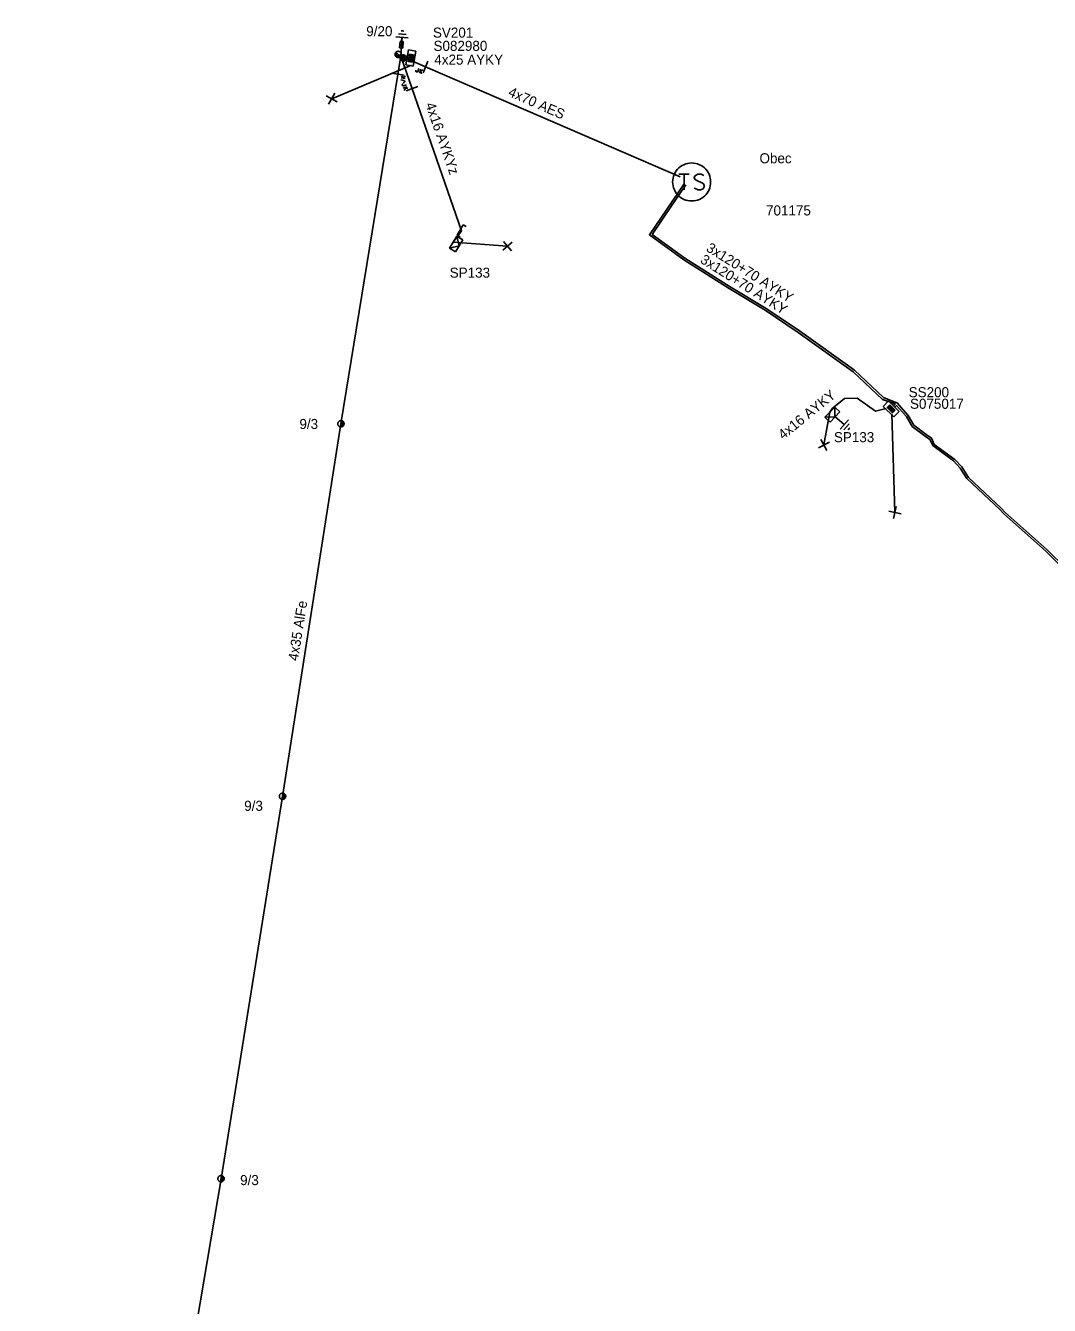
# Model space of a CAD drawing. Extents: x -788458 to -786145, y -1154772 to -1152372.
# Drawn here: x -786583.3 to -786481.4, y -1153446 to -1153318.7 of the extents above; entities that cross this region are included whole.
import ezdxf

# ---------------------------------------------------------------- set-up
doc = ezdxf.new("R2010")
doc.units = 0
for name, color, linetype in [('Vrstva 1', 7, 'Continuous'), ('Vrstva 12', 7, 'Continuous'), ('Vrstva 13', 7, 'Continuous'), ('Vrstva 14', 7, 'Continuous'), ('Vrstva 15', 7, 'Continuous'), ('Vrstva 16', 7, 'Continuous'), ('Vrstva 18', 7, 'Continuous'), ('Vrstva 2', 7, 'Continuous'), ('Vrstva 25', 7, 'Continuous'), ('Vrstva 26', 7, 'Continuous'), ('Vrstva 27', 7, 'Continuous'), ('Vrstva 28', 7, 'Continuous'), ('Vrstva 29', 7, 'Continuous'), ('Vrstva 30', 7, 'Continuous'), ('Vrstva 31', 7, 'Continuous'), ('Vrstva 33', 7, 'Continuous'), ('Vrstva 34', 7, 'Continuous'), ('Vrstva 5', 7, 'Continuous'), ('Vrstva 50', 7, 'Continuous'), ('Vrstva 51', 7, 'Continuous'), ('Vrstva 52', 7, 'Continuous'), ('Vrstva 54', 7, 'Continuous'), ('Vrstva 55', 7, 'Continuous'), ('Vrstva 59', 7, 'Continuous'), ('Vrstva 6', 7, 'Continuous'), ('Vrstva 8', 7, 'Continuous'), ('Vrstva 9', 7, 'Continuous')]:
    doc.layers.add(name, color=color, linetype=linetype)

# ---------------------------------------------------------------- blocks, each defined once
blk = doc.blocks.new('NN440')
at = {"layer": 'Vrstva 2'}
for points in [[(0.63, 0), (0.63, 0.06), (0.62, 0.13), (0.6, 0.19), (0.58, 0.25), (0.55, 0.31), (0.51, 0.37), (0.47, 0.42), (0.42, 0.46), (0.37, 0.51), (0.32, 0.54), (0.26, 0.57), (0.2, 0.59), (0.13, 0.61), (0.07, 0.62), (0, 0.63), (-0.06, 0.62), (-0.13, 0.61), (-0.19, 0.59), (-0.26, 0.57), (-0.31, 0.54), (-0.37, 0.51), (-0.42, 0.46), (-0.47, 0.42), (-0.51, 0.37), (-0.54, 0.31), (-0.57, 0.25), (-0.6, 0.19), (-0.62, 0.13), (-0.63, 0.06), (-0.63, 0), (-0.63, -0.07), (-0.62, -0.14), (-0.6, -0.2), (-0.57, -0.26), (-0.54, -0.32), (-0.51, -0.37), (-0.47, -0.43), (-0.42, -0.47), (-0.37, -0.51), (-0.31, -0.55), (-0.26, -0.58), (-0.19, -0.6), (-0.13, -0.62), (-0.06, -0.63), (0, -0.63), (0.07, -0.63), (0.13, -0.62), (0.2, -0.6), (0.26, -0.58), (0.32, -0.55), (0.37, -0.51), (0.42, -0.47), (0.47, -0.43), (0.51, -0.37), (0.55, -0.32), (0.58, -0.26), (0.6, -0.2), (0.62, -0.14), (0.63, -0.07), (0.63, 0)], [(-0.63, 0), (0.63, 0)], [(-0.6, -0.18), (0.57, -0.18)], [(-0.51, -0.32), (0.5, -0.32)], [(-0.37, -0.47), (0.35, -0.47)]]:
    blk.add_lwpolyline(points, dxfattribs=at)
blk = doc.blocks.new('NN450')
at = {"layer": 'Vrstva 2'}
for points in [[(0, 0), (0, 0.07), (-0.01, 0.13), (-0.03, 0.19), (-0.05, 0.25), (-0.08, 0.31), (-0.12, 0.37), (-0.16, 0.42), (-0.21, 0.46), (-0.26, 0.51), (-0.31, 0.54), (-0.37, 0.57), (-0.43, 0.59), (-0.5, 0.61), (-0.56, 0.62), (-0.63, 0.62), (-0.69, 0.62), (-0.75, 0.61), (-0.82, 0.59), (-0.88, 0.57), (-0.94, 0.54), (-0.99, 0.51), (-1.04, 0.46), (-1.09, 0.42), (-1.13, 0.37), (-1.17, 0.31), (-1.2, 0.25), (-1.22, 0.19), (-1.24, 0.13), (-1.25, 0.07), (-1.25, 0), (-1.25, -0.07), (-1.24, -0.13), (-1.22, -0.19), (-1.2, -0.25), (-1.17, -0.31), (-1.13, -0.37), (-1.09, -0.42), (-1.04, -0.46), (-0.99, -0.51), (-0.94, -0.54), (-0.88, -0.57), (-0.82, -0.59), (-0.75, -0.61), (-0.69, -0.62), (-0.62, -0.63), (-0.56, -0.62), (-0.5, -0.61), (-0.43, -0.59), (-0.37, -0.57), (-0.31, -0.54), (-0.26, -0.51), (-0.21, -0.46), (-0.16, -0.42), (-0.12, -0.37), (-0.08, -0.31), (-0.05, -0.25), (-0.03, -0.19), (-0.01, -0.13), (0, -0.07), (0, 0)], [(1.25, 0), (1.25, 0.07), (1.24, 0.13), (1.22, 0.19), (1.2, 0.25), (1.17, 0.31), (1.13, 0.37), (1.09, 0.42), (1.04, 0.46), (0.99, 0.51), (0.94, 0.54), (0.88, 0.57), (0.82, 0.59), (0.75, 0.61), (0.69, 0.62), (0.62, 0.62), (0.56, 0.62), (0.5, 0.61), (0.43, 0.59), (0.37, 0.57), (0.31, 0.54), (0.26, 0.51), (0.21, 0.46), (0.16, 0.42), (0.12, 0.37), (0.08, 0.31), (0.05, 0.25), (0.03, 0.19), (0.01, 0.13), (0, 0.07), (0, 0), (0, -0.07), (0.01, -0.13), (0.03, -0.19), (0.05, -0.25), (0.08, -0.31), (0.12, -0.37), (0.16, -0.42), (0.21, -0.46), (0.26, -0.51), (0.31, -0.54), (0.37, -0.57), (0.43, -0.59), (0.5, -0.61), (0.56, -0.62), (0.63, -0.63), (0.69, -0.62), (0.75, -0.61), (0.82, -0.59), (0.88, -0.57), (0.94, -0.54), (0.99, -0.51), (1.04, -0.46), (1.09, -0.42), (1.13, -0.37), (1.17, -0.31), (1.2, -0.25), (1.22, -0.19), (1.24, -0.13), (1.25, -0.07), (1.25, 0)], [(-1.25, 0), (1.25, 0)], [(-1.23, -0.16), (-0.02, -0.16)], [(-1.16, -0.32), (-0.09, -0.32)], [(-1.03, -0.47), (-0.22, -0.47)], [(0.02, -0.16), (1.23, -0.16)], [(0.09, -0.32), (1.16, -0.32)], [(0.22, -0.47), (1.03, -0.47)]]:
    blk.add_lwpolyline(points, dxfattribs=at)
blk = doc.blocks.new('NN840')
at = {"layer": 'Vrstva 15'}
for points in [[(0, 0.62), (0, -0.63)], [(-0.75, -0.71), (-0.75, -0.66)], [(-0.73, -0.76), (-0.75, -0.71)], [(-0.66, -0.8), (-0.73, -0.76)], [(-0.63, -0.8), (-0.66, -0.8)], [(-0.56, -0.76), (-0.63, -0.8)], [(-0.54, -0.71), (-0.56, -0.76)], [(-0.54, -0.38), (-0.54, -0.71)], [(-0.33, -0.38), (-0.33, -0.8)], [(-0.33, -0.64), (-0.13, -0.38)], [(-0.26, -0.56), (-0.09, -0.8)]]:
    blk.add_lwpolyline(points, dxfattribs=at)
blk = doc.blocks.new('NN800')
at = {"layer": 'Vrstva 1'}
for points in [[(-0.44, 0.44), (0.44, -0.44)], [(-0.44, -0.44), (0.44, 0.44)]]:
    blk.add_lwpolyline(points, dxfattribs=at)
blk = doc.blocks.new('NN820')
at = {"layer": 'Vrstva 13'}
for points in [[(0, 0), (0, -1.05)], [(-0.16, -0.81), (0.16, -0.81)], [(-0.16, -1.47), (-0.16, -0.81)], [(0, -1.05), (-0.06, -0.93)], [(0, -1.05), (0.06, -0.93)], [(0.16, -0.81), (0.16, -1.47)], [(0.16, -1.47), (-0.16, -1.47)], [(0, -1.47), (0, -1.87)]]:
    blk.add_lwpolyline(points, dxfattribs=at)
blk = doc.blocks.new('NN620')
at = {"layer": 'Vrstva 8'}
for points in [[(0.75, 0), (-0.75, 0)], [(-0.75, 0), (-0.75, -0.75)], [(0.75, -0.75), (0.75, 0)], [(-0.75, -0.75), (0.75, -0.75)], [(0.37, -0.18), (-0.38, -0.18)], [(-0.38, -0.18), (-0.38, -0.56)], [(-0.38, -0.56), (0.37, -0.56)], [(0.32, -0.23), (-0.33, -0.23)], [(-0.33, -0.23), (-0.33, -0.51)], [(-0.33, -0.51), (0.32, -0.51)], [(0.27, -0.27), (-0.28, -0.27)], [(-0.28, -0.27), (-0.28, -0.46)], [(-0.28, -0.46), (0.27, -0.46)], [(0.23, -0.32), (-0.23, -0.32)], [(-0.23, -0.32), (-0.23, -0.42)], [(-0.23, -0.42), (0.23, -0.42)], [(-0.19, -0.37), (0.19, -0.37)], [(0.23, -0.42), (0.23, -0.32)], [(0.27, -0.46), (0.27, -0.27)], [(0.32, -0.51), (0.32, -0.23)], [(0.37, -0.56), (0.37, -0.18)]]:
    blk.add_lwpolyline(points, dxfattribs=at)
blk = doc.blocks.new('NN630')
at = {"layer": 'Vrstva 9'}
for points in [[(0, -0.7), (-0.7, 0)], [(-0.7, -0.7), (-0.7, 0), (0.7, 0), (0.7, -0.7)], [(-0.7, -0.7), (0.7, -0.7)], [(0, -0.7), (0.7, 0)]]:
    blk.add_lwpolyline(points, dxfattribs=at)
blk = doc.blocks.new('NN810')
at = {"layer": 'Vrstva 14'}
for points in [[(0, -0.64), (0, -1.89)], [(0.63, -1.89), (-0.62, -1.89)], [(0.39, -2.2), (-0.4, -2.2)], [(0, -2.52), (-0.12, -2.52)], [(0.14, -2.52), (0, -2.52)]]:
    blk.add_lwpolyline(points, dxfattribs=at)
blk = doc.blocks.new('NN610')
at = {"layer": 'Vrstva 6'}
for points in [[(1.88, 0), (1.87, 0.2), (1.84, 0.39), (1.79, 0.58), (1.72, 0.77), (1.63, 0.94), (1.52, 1.11), (1.4, 1.26), (1.26, 1.4), (1.1, 1.53), (0.94, 1.63), (0.76, 1.72), (0.58, 1.8), (0.19, 1.88), (0.19, 1.88), (-0.01, 1.89), (-0.21, 1.88), (-0.4, 1.85), (-0.59, 1.8), (-0.78, 1.72), (-0.95, 1.63), (-1.12, 1.53), (-1.27, 1.4), (-1.41, 1.26), (-1.54, 1.11), (-1.64, 0.94), (-1.73, 0.77), (-1.8, 0.58), (-1.86, 0.39), (-1.89, 0.2), (-1.9, 0), (-1.89, -0.2), (-1.86, -0.39), (-1.8, -0.58), (-1.73, -0.77), (-1.64, -0.95), (-1.54, -1.11), (-1.41, -1.27), (-1.27, -1.41), (-1.12, -1.53), (-0.95, -1.64), (-0.78, -1.73), (-0.59, -1.8), (-0.4, -1.85), (-0.21, -1.88), (-0.01, -1.89), (0.19, -1.88), (0.39, -1.85), (0.58, -1.8), (0.76, -1.73), (0.94, -1.64), (1.1, -1.53), (1.26, -1.41), (1.4, -1.27), (1.52, -1.11), (1.63, -0.95), (1.72, -0.77), (1.79, -0.58), (1.84, -0.39), (1.87, -0.2), (1.88, 0)], [(-1.27, 0.78), (-0.26, 0.78)], [(-0.76, 0.78), (-0.76, -0.79)], [(1.19, 0.66), (0.94, 0.78), (0.62, 0.78), (0.37, 0.66), (0.24, 0.47), (0.24, 0.4), (0.37, 0.22), (1.12, -0.16), (1.25, -0.32), (1.25, -0.48), (1.12, -0.67), (0.87, -0.79), (0.62, -0.79), (0.49, -0.73), (0.24, -0.6)]]:
    blk.add_lwpolyline(points, dxfattribs=at)
blk = doc.blocks.new('NN515')
at = {"layer": 'Vrstva 2'}
for points in [[(-0.59, 0.18), (0.59, 0.18)], [(-0.59, 0.18), (-0.59, -0.18)], [(0.59, 0.18), (0.59, -0.18)]]:
    blk.add_lwpolyline(points, dxfattribs=at)

msp = doc.modelspace()

# ---------------------------------------------------------------- linework, layer by layer
at = {"layer": 'Vrstva 1'}
msp.add_lwpolyline([(-786489.69, -1153518.84), (-786509.16, -1153535.21), (-786526.82, -1153550.01), (-786583.29, -1153546.79), (-786577.19, -1153510.6), (-786570.4, -1153472.16), (-786563.85, -1153433.39), (-786557.73, -1153395.36), (-786551.92, -1153358.3), (-786545.97, -1153321.74)], dxfattribs=at)
at = {"layer": 'Vrstva 5'}
for points in [[(-786545.97, -1153321.74), (-786545.31, -1153321.77)], [(-786496.97, -1153356.51), (-786496.78, -1153356.35), (-786497.05, -1153356.23), (-786498.04, -1153355.87), (-786500.95, -1153353.13), (-786506.43, -1153349.23), (-786509.71, -1153347), (-786513.31, -1153344.85), (-786517.82, -1153342), (-786521.23, -1153339.5), (-786517.78, -1153334.43)], [(-786477.94, -1153374.5), (-786481.67, -1153370.84), (-786485.85, -1153367.12), (-786486.23, -1153366.7), (-786489.49, -1153363.63), (-786490.16, -1153362.6), (-786490.84, -1153361.86), (-786492.89, -1153360.35), (-786493.17, -1153359.72), (-786493.69, -1153359.37), (-786494.94, -1153358.43), (-786495.5, -1153357.47), (-786496.23, -1153356.64), (-786496.55, -1153356.24), (-786497.94, -1153355.69), (-786500.83, -1153352.97), (-786506.31, -1153349.07), (-786509.61, -1153346.84), (-786513.21, -1153344.67), (-786517.7, -1153341.84), (-786520.95, -1153339.46), (-786519.03, -1153336.63), (-786518.67, -1153336.1), (-786517.62, -1153334.55)], [(-786478.1, -1153374.62), (-786481.81, -1153370.98), (-786485.99, -1153367.26), (-786486.37, -1153366.84), (-786489.65, -1153363.75), (-786490.32, -1153362.72), (-786490.98, -1153362), (-786493.05, -1153360.47), (-786493.33, -1153359.86), (-786493.81, -1153359.53), (-786495.1, -1153358.57), (-786495.66, -1153357.59), (-786496.38, -1153356.77), (-786496.64, -1153356.49), (-786496.83, -1153356.65)]]:
    msp.add_lwpolyline(points, dxfattribs=at)
at = {"layer": 'Vrstva 50'}
msp.add_lwpolyline([(-786518.16, -1153333.74), (-786545.97, -1153321.74)], dxfattribs=at)
at = {"layer": 'Vrstva 52'}
msp.add_lwpolyline([(-786497.67, -1153356.77), (-786498.73, -1153357.06), (-786500.56, -1153355.76), (-786501.82, -1153355.79), (-786502.54, -1153356.37), (-786503.02, -1153356.76), (-786503.28, -1153357.14)], dxfattribs=at)
at = {"layer": 'Vrstva 54'}
msp.add_lwpolyline([(-786545.97, -1153321.74), (-786539.91, -1153339.11), (-786540.75, -1153340.24)], dxfattribs=at)
at = {"layer": 'Vrstva 59'}
for points in [[(-786544.89, -1153322.63), (-786552.84, -1153325.97)], [(-786540.75, -1153340.24), (-786535.35, -1153340.65)], [(-786503.28, -1153357.14), (-786503.88, -1153360.41)], [(-786497.12, -1153357.3), (-786496.81, -1153367.13)]]:
    msp.add_lwpolyline(points, dxfattribs=at)

# ---------------------------------------------------------------- block references
at = {"layer": 'Vrstva 13', "yscale": 0.5000000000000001}
for name, p, xscale, rotation in [('NN450', (-786545.97, -1153321.74), 0.49999999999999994, -34.8330138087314), ('NN440', (-786551.92, -1153358.3), 0.49999999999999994, 79.82778887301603), ('NN440', (-786557.73, -1153395.36), 0.5, 79.82752495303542), ('NN440', (-786563.85, -1153433.39), 0.5, 79.82752497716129)]:
    msp.add_blockref(name, p, dxfattribs=dict(at, xscale=xscale, rotation=rotation))
at = {"layer": 'Vrstva 13', "rotation": 59.3345305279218}
msp.add_blockref('NN515', (-786539.91, -1153339.11), dxfattribs=at)
at = {"layer": 'Vrstva 15'}
for p, rotation in [((-786545.97, -1153321.74), 175.97010557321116), ((-786503.28, -1153357.14), 48.806544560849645)]:
    msp.add_blockref('NN810', p, dxfattribs=dict(at, rotation=rotation))
at = {"layer": 'Vrstva 16', "rotation": 176.48117777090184}
msp.add_blockref('NN820', (-786545.97, -1153321.74), dxfattribs=at)
at = {"layer": 'Vrstva 18'}
for p, rotation in [((-786543.51, -1153322.8), -22.3541833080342), ((-786546.26, -1153323.51), 80.90415572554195), ((-786544.85, -1153324.96), -70.76722284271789)]:
    msp.add_blockref('NN840', p, dxfattribs=dict(at, rotation=rotation))
at = {"layer": 'Vrstva 25'}
msp.add_blockref('NN610', (-786517.02, -1153334.25), dxfattribs=at)
at = {"layer": 'Vrstva 28'}
for p, rotation in [((-786545.33, -1153321.85), 79.31508768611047), ((-786496.92, -1153356.56), -44.514454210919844)]:
    msp.add_blockref('NN620', p, dxfattribs=dict(at, rotation=rotation))
at = {"layer": 'Vrstva 31'}
for p, rotation in [((-786540.75, -1153340.23), 58.8515695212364), ((-786503.28, -1153357.14), 46.14119931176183)]:
    msp.add_blockref('NN630', p, dxfattribs=dict(at, rotation=rotation))
at = {"layer": 'Vrstva 34'}
for p, rotation in [((-786552.84, -1153325.97), -74.04094442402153), ((-786535.35, -1153340.64), 175.65814165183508), ((-786503.88, -1153360.41), 73.26410833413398), ((-786496.81, -1153367.13), 122.95228332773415)]:
    msp.add_blockref('NN800', p, dxfattribs=dict(at, rotation=rotation))

# ---------------------------------------------------------------- texts
at = {"layer": 'Vrstva 12'}
for s, p in [('9/20', (-786549.4, -1153319.75)), ('9/3', (-786556.05, -1153358.82)), ('9/3', (-786561.54, -1153396.8)), ('9/3', (-786561.95, -1153434.03))]:
    msp.add_text(s, height=1, dxfattribs=at).set_placement(p)
at = {"layer": 'Vrstva 2'}
msp.add_text('4x35 AlFe', height=1, rotation=81.09, dxfattribs=at).set_placement((-786556.19, -1153381.93))
at = {"layer": 'Vrstva 26'}
msp.add_text('701175', height=1, dxfattribs=at).set_placement((-786509.63, -1153337.58))
at = {"layer": 'Vrstva 27'}
msp.add_text('Obec', height=1, dxfattribs=at).set_placement((-786510.28, -1153332.39))
at = {"layer": 'Vrstva 29'}
for s, p in [('S082980', (-786542.71, -1153321.21)), ('S075017', (-786495.31, -1153356.81))]:
    msp.add_text(s, height=1, dxfattribs=at).set_placement(p)
at = {"layer": 'Vrstva 30'}
for s, p in [('SV201', (-786542.77, -1153319.89)), ('SS200', (-786495.44, -1153355.66))]:
    msp.add_text(s, height=1, dxfattribs=at).set_placement(p)
at = {"layer": 'Vrstva 33'}
for p in [(-786541.1, -1153343.77), (-786502.88, -1153360.13)]:
    msp.add_text('SP133', height=1, dxfattribs=at).set_placement(p)
at = {"layer": 'Vrstva 51'}
msp.add_text('4x70 AES', height=1, rotation=336.369, dxfattribs=at).set_placement((-786535.37, -1153325.66))
at = {"layer": 'Vrstva 54'}
msp.add_text('4x16 AYKY', height=1, rotation=38.95, dxfattribs=at).set_placement((-786507.93, -1153359.92))
at = {"layer": 'Vrstva 55'}
msp.add_text('4x16 AYKYz', height=1, rotation=289.214, dxfattribs=at).set_placement((-786543.54, -1153326.53))
at = {"layer": 'Vrstva 6'}
msp.add_text('4x25 AYKY', height=1, dxfattribs=at).set_placement((-786542.63, -1153322.58))
for rotation, p in [(327.9, (-786515.67, -1153341.06)), (327.743, (-786516.26, -1153342.22))]:
    msp.add_text('3x120+70 AYKY', height=1, rotation=rotation, dxfattribs=at).set_placement(p)

doc.saveas('drawing.dxf')
